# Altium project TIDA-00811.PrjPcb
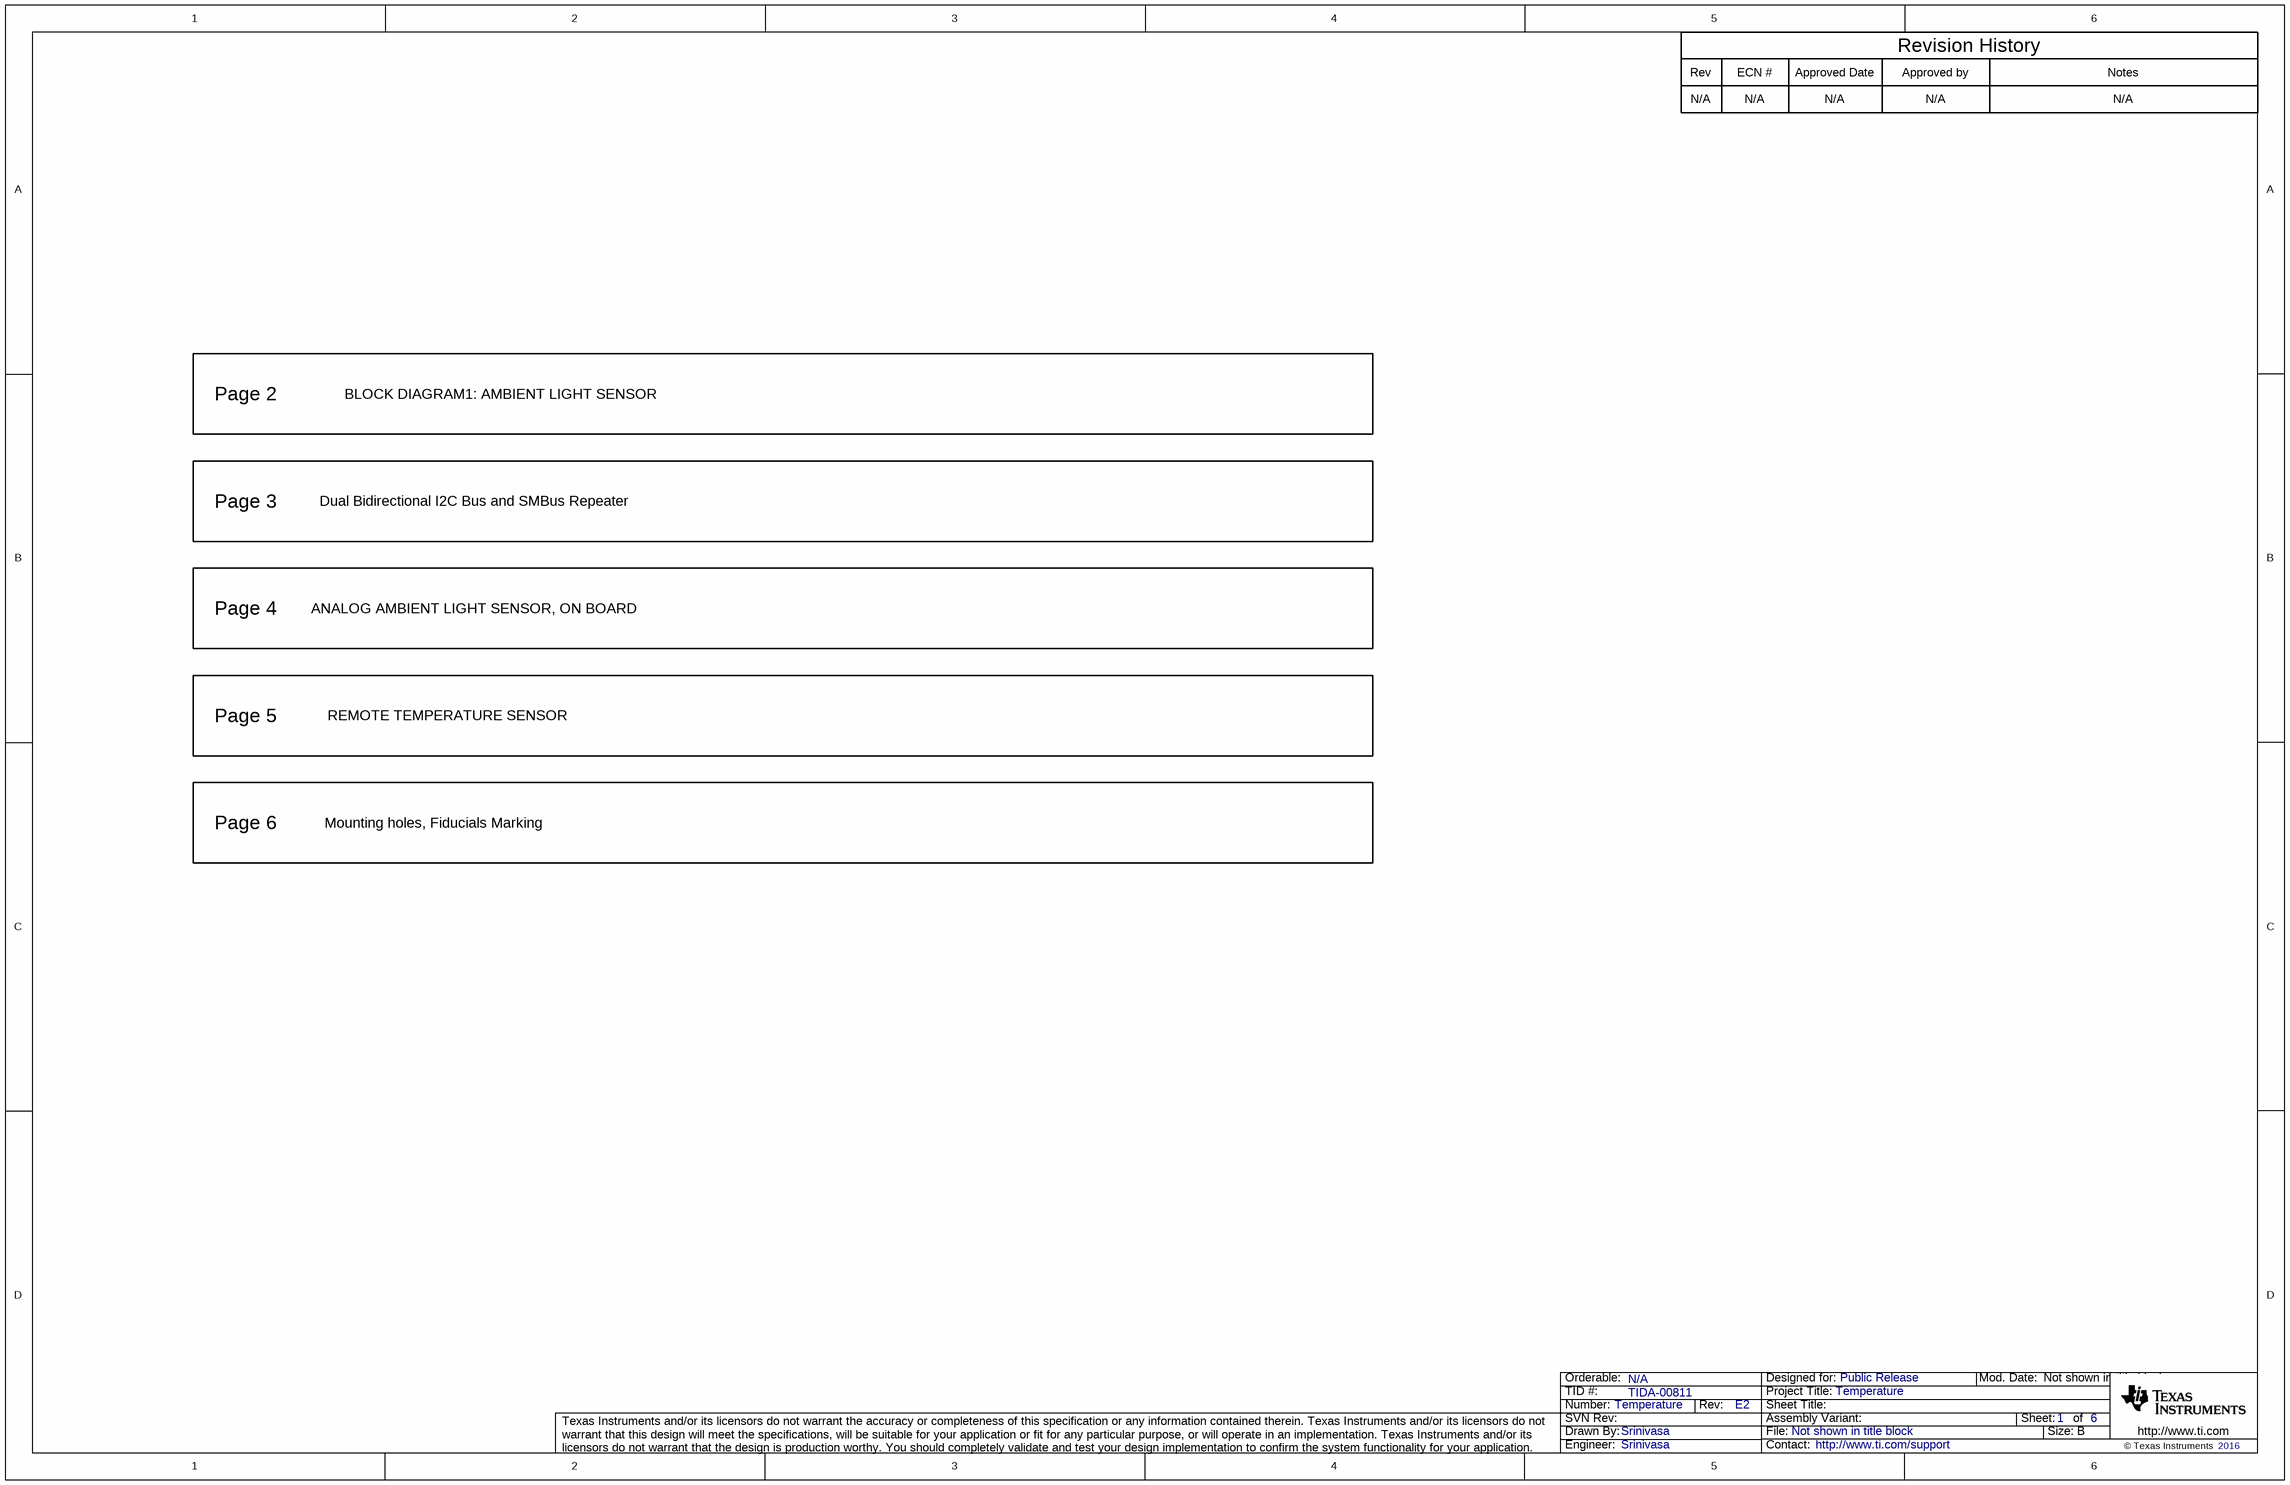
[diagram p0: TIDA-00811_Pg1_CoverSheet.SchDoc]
CopyrightYear: 2016; EVM_orderable: N/A; PCB_Layout: Manjunath M; PCB_Rev: E2; PRJ_Customer: Public Release; PRJ_Engineer: Srinivasa; PRJ_Number: Temperature; PRJ_Title: Temperature; SCH_Rev: E2; TechSupport: http://www.ti.com/support; TID: TIDA-00811
6 sheets, 185 parts. Net scope: flat (ports and power ports of the same name join across sheets).
Board file: TIDA-00811_PCB.PcbDoc
Sheets:
  TIDA-00811_Pg1_CoverSheet.SchDoc
  TIDA-00811_Pg2_Block Diagram.SchDoc
  TIDA-00811_Pg3.SchDoc
  TIDA-00811_Pg4.SchDoc
  TIDA-00811_Pg5.SchDoc
  TIDA-00811_Pg6_EVM_Hardware.SchDoc

## Sheet TIDA-00811_Pg1_CoverSheet.SchDoc
size 431 x 279 mm; Date: Not shown in title block; ApprovedBy: Not shown in title block; CheckedBy: Not shown in title block; Author: Not shown in title block; CompanyName: Not shown in title block; DrawnBy: Srinivasa; Engineer: Not shown in title block; Organization: Not shown in title block; Address1: Not shown in title block; Address2: Not shown in title block; Address3: Not shown in title block; Address4: Not shown in title block; DocumentNumber: 1; Revision: Use project parameter SCH_Rev; SheetNumber: 1; SheetTotal: 6; PageSetup: Record=PageOptions¦CenterHorizontal=True¦CenterVertical=True¦PrintScale=1.00¦XCorrection=1.00¦YCorrection=1.00¦PrintKind=0¦BorderSize=5000000¦LeftOffset=0¦BottomOffset=0¦Orientation=2¦PaperLength=1000¦PaperWidth=1000¦Scale=100¦PaperSource=15¦PrintQuality=600¦MediaType=1¦DitherType=10¦PaperKind=Letter¦PrintScaleMode=1

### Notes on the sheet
- Rev
- N/A
- ECN #
- Approved Date
- Approved by
- Revision History
- Notes
- Page 2
- BLOCK DIAGRAM1: AMBIENT LIGHT SENSOR
- Page 3
- Dual Bidirectional I2C Bus and SMBus Repeater
- Page 4
- ANALOG AMBIENT LIGHT SENSOR, ON BOARD
- Page 5
- REMOTE TEMPERATURE SENSOR
- Page 6
- Mounting holes, Fiducials Marking

## Sheet TIDA-00811_Pg2_Block Diagram.SchDoc
size 431 x 279 mm; Date: Not shown in title block; ApprovedBy: Not shown in title block; CheckedBy: Not shown in title block; Author: Not shown in title block; CompanyName: Not shown in title block; DrawnBy: Srinivasa; Engineer: Not shown in title block; Organization: Not shown in title block; Address1: Not shown in title block; Address2: Not shown in title block; Address3: Not shown in title block; Address4: Not shown in title block; DocumentNumber: 1; Revision: Use project parameter SCH_Rev; SheetNumber: 2; SheetTotal: 6; PageSetup: Record=PageOptions¦CenterHorizontal=True¦CenterVertical=True¦PrintScale=1.00¦XCorrection=1.00¦YCorrection=1.00¦PrintKind=0¦BorderSize=5000000¦LeftOffset=0¦BottomOffset=0¦Orientation=2¦PaperLength=1000¦PaperWidth=1000¦Scale=100¦PaperSource=15¦PrintQuality=600¦MediaType=1¦DitherType=10¦PaperKind=Letter¦PrintScaleMode=1
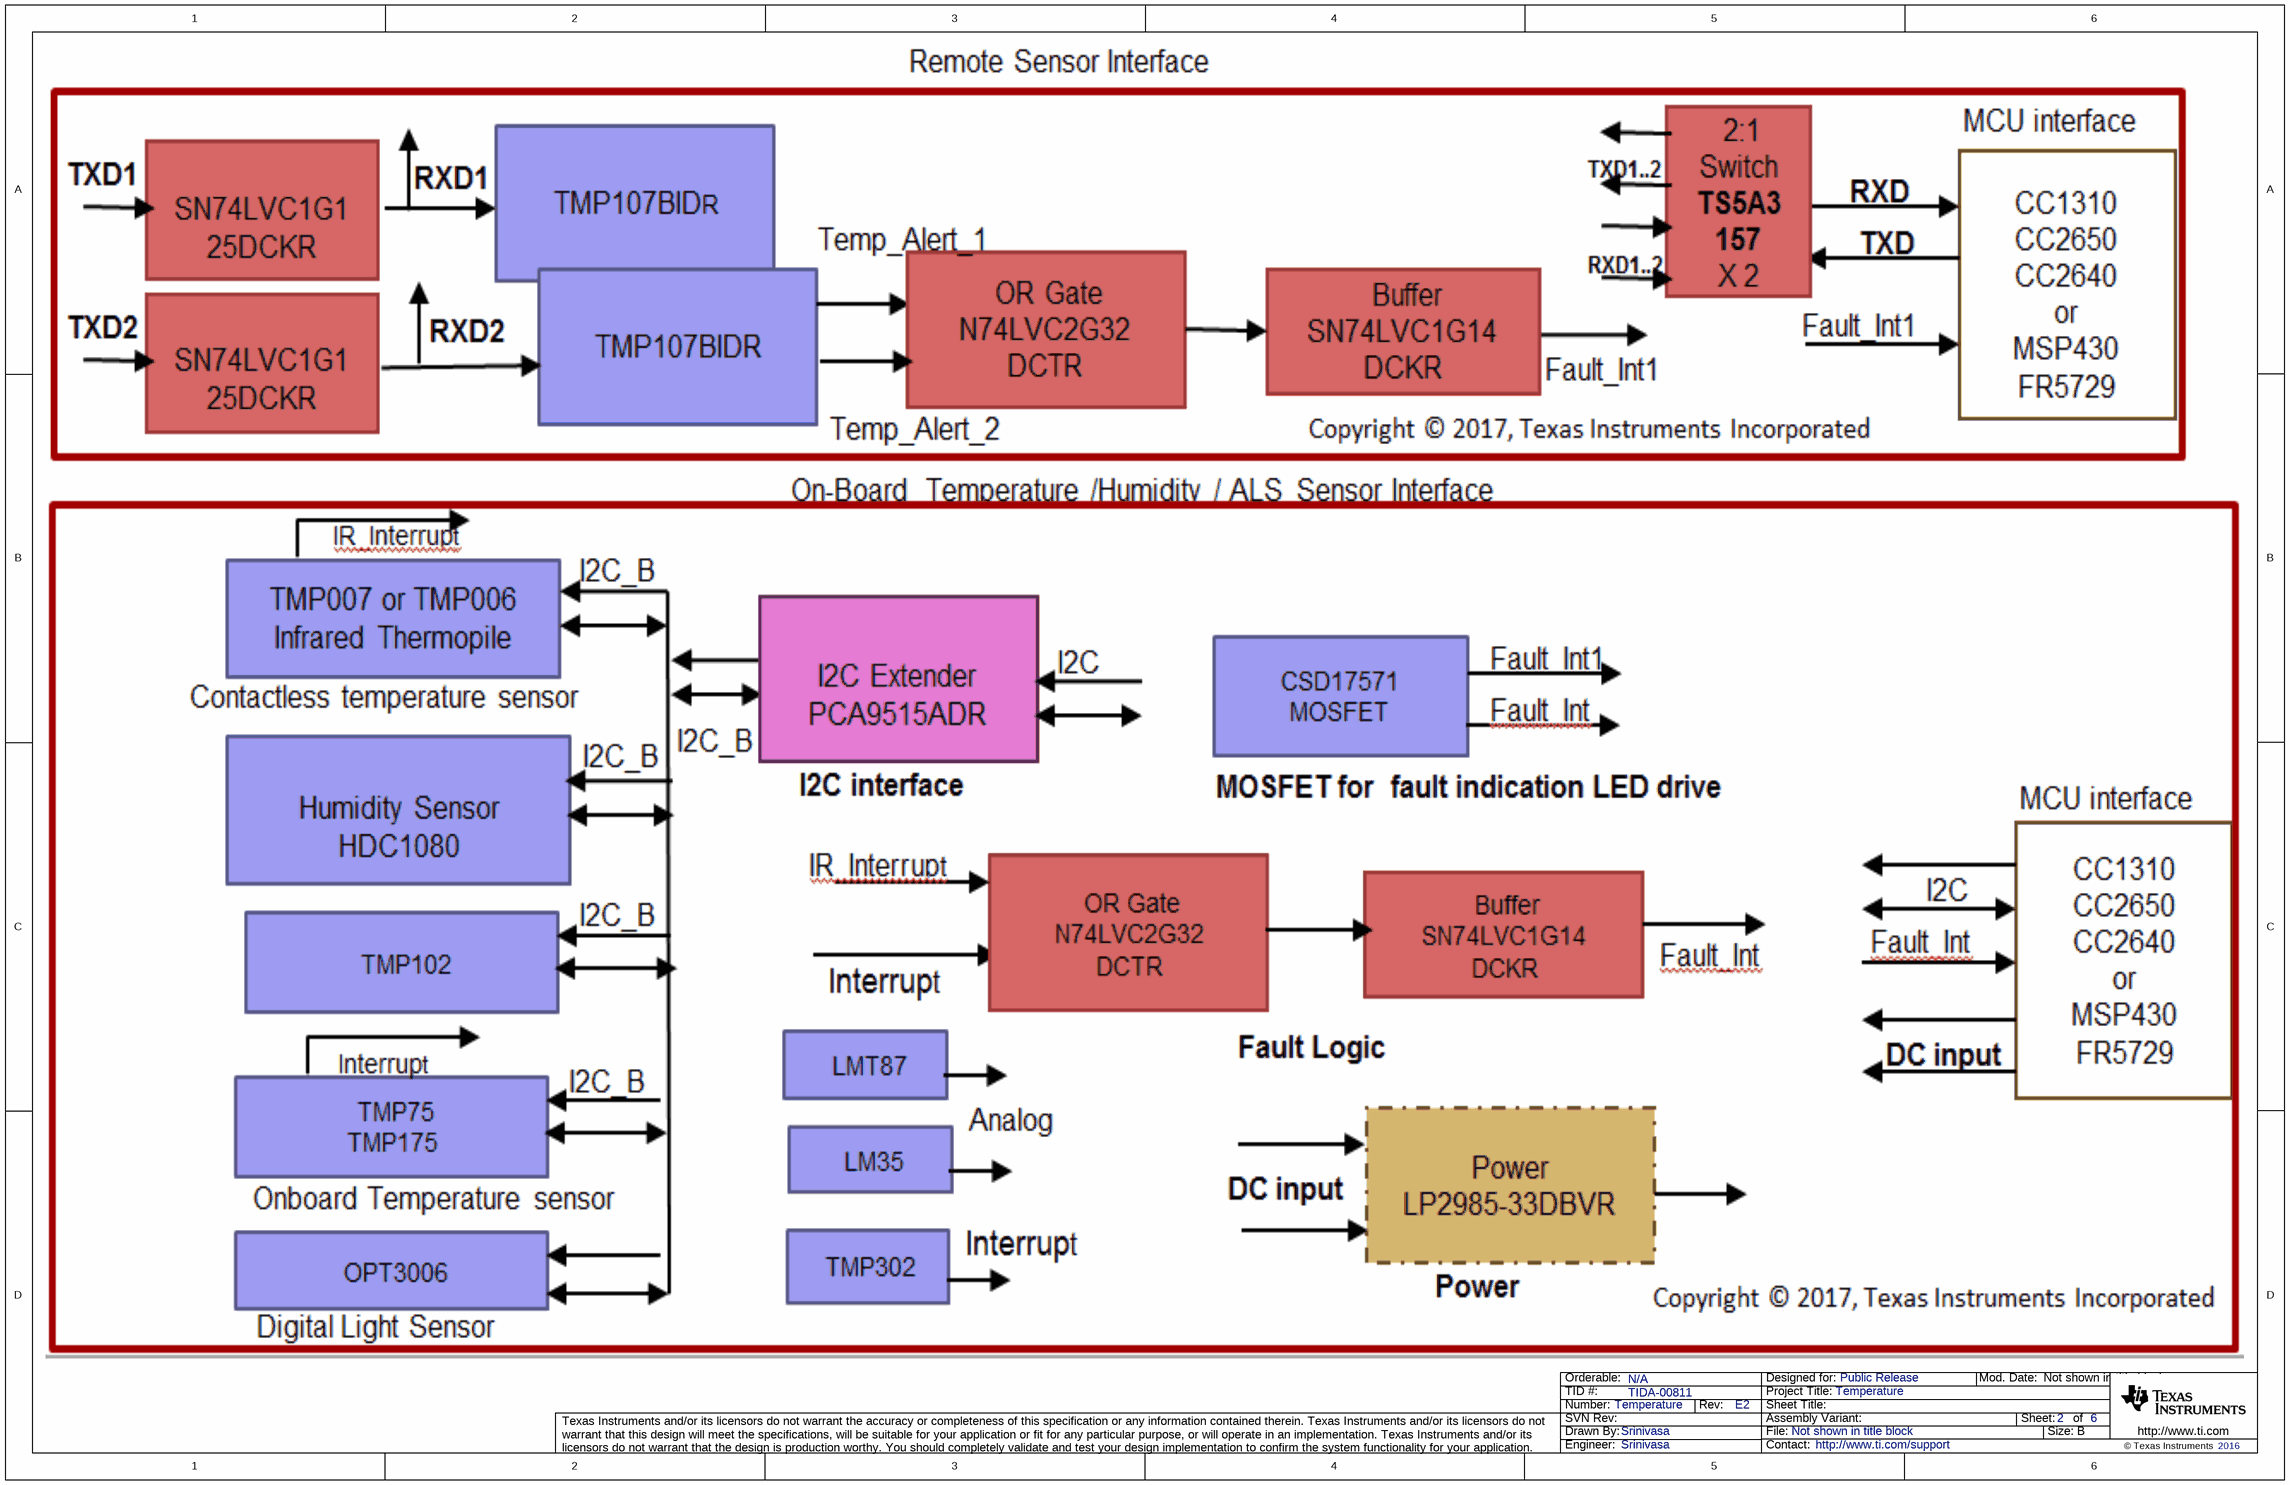
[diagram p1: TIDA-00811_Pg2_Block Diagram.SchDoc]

## Sheet TIDA-00811_Pg3.SchDoc
size 431 x 279 mm; Date: Not shown in title block; ApprovedBy: Not shown in title block; CheckedBy: Not shown in title block; Author: Not shown in title block; CompanyName: Not shown in title block; DrawnBy: Srinivasa; Engineer: Not shown in title block; Organization: Not shown in title block; Address1: Not shown in title block; Address2: Not shown in title block; Address3: Not shown in title block; Address4: Not shown in title block; DocumentNumber: 1; Revision: Use project parameter SCH_Rev; SheetNumber: 3; SheetTotal: 6; PageSetup: Record=PageOptions¦CenterHorizontal=True¦CenterVertical=True¦PrintScale=1.00¦XCorrection=1.00¦YCorrection=1.00¦PrintKind=0¦BorderSize=5000000¦LeftOffset=0¦BottomOffset=0¦Orientation=2¦PaperLength=1000¦PaperWidth=1000¦Scale=100¦PaperSource=15¦PrintQuality=600¦MediaType=1¦DitherType=10¦PaperKind=Letter¦PrintScaleMode=1
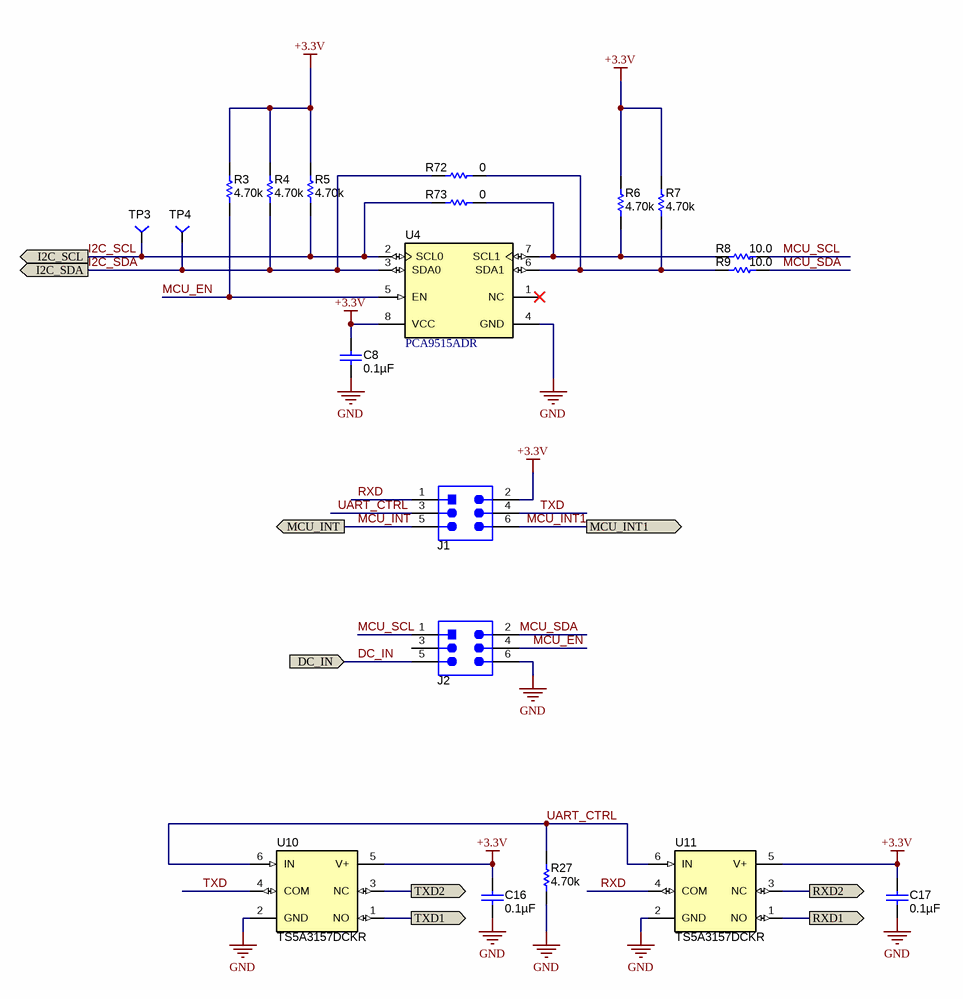
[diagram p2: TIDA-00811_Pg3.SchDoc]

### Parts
C8  ValueDisplayed: 0.1µF  [0603]  (hidden comment: 06033C104JAT2A)
C16  ValueDisplayed: 0.1µF  [0603]  (hidden comment: 06033C104JAT2A)
C17  ValueDisplayed: 0.1µF  [0603]  (hidden comment: 06033C104JAT2A)
J1  61300621121  [Mill-Max_802-10-006-10-001000]  (value not drawn)
J2  61300621121  [Mill-Max_802-10-006-10-001000]  (value not drawn)
R3  ValueDisplayed: 4.70k  [0603]  (hidden comment: RC0603FR-074K7L)
R4  ValueDisplayed: 4.70k  [0603]  (hidden comment: RC0603FR-074K7L)
R5  ValueDisplayed: 4.70k  [0603]  (hidden comment: RC0603FR-074K7L)
R6  ValueDisplayed: 4.70k  [0603]  (hidden comment: RC0603FR-074K7L)
R7  ValueDisplayed: 4.70k  [0603]  (hidden comment: RC0603FR-074K7L)
R8  ValueDisplayed: 10.0  [0603]  (hidden comment: CRCW060310R0FKEA)
R9  ValueDisplayed: 10.0  [0603]  (hidden comment: CRCW060310R0FKEA)
R27  ValueDisplayed: 4.70k  [0603]  (hidden comment: RC0603FR-074K7L)
R72  ValueDisplayed: 0  [0603]  (hidden comment: RC0603JR-070RL)
R73  ValueDisplayed: 0  [0603]  (hidden comment: RC0603JR-070RL)
TP3  TP-5001-BLACK  [TH-40]  (value not drawn)
TP4  TP-5001-BLACK  [TH-40]  (value not drawn)
U4  PCA9515ADR  [D0008A_N]
U10  TS5A3157DCKR  [DCK0006A_N]
U11  TS5A3157DCKR  [DCK0006A_N]

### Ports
DC_IN, I2C_SCL (out), I2C_SDA (out), MCU_INT1 (out), MCU_INT (out), RXD1 (out), RXD2 (out), TXD1 (out), TXD2 (out)

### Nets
+3.3V: C8.1 C16.1 C17.1 J1.2 R3.2 R4.2 R5.2 R6.2 R7.2 U4.8(VCC) U10.5(V+) U11.5(V+)
GND: C8.2 C16.2 C17.2 J2.6 R27.1 U4.4(GND) U10.2(GND) U11.2(GND)
DC_IN: J2.5 ; port DC_IN
I2C_SCL: R5.1 R73.2 TP3.1 U4.2(SCL0) ; port I2C_SCL
I2C_SDA: R4.1 R72.2 TP4.1 U4.3(SDA0) ; port I2C_SDA
MCU_EN: J2.4 R3.1 U4.5(EN)
MCU_INT: J1.5 ; port MCU_INT
MCU_INT1: J1.6 ; port MCU_INT1
MCU_SCL: J2.1 R8.2
MCU_SDA: J2.2 R9.2
RXD: J1.1 U11.4(COM)
RXD1: U11.1(NO) ; port RXD1
RXD2: U11.3(NC) ; port RXD2
TXD: J1.4 U10.4(COM)
TXD1: U10.1(NO) ; port TXD1
TXD2: U10.3(NC) ; port TXD2
UART_CTRL: J1.3 R27.2 U10.6(IN) U11.6(IN)
NetR6_1: R6.1 R8.1 R73.1 U4.7(SCL1)
NetR7_1: R7.1 R9.1 R72.1 U4.6(SDA1)

Not connected (* = marked no-connect by the designer): J2 3; U4 1(NC)*

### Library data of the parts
C8 C16 C17 = 06033C104JAT2A: CAP, CERM, 0.1 µF, 25 V, +/- 5%, X7R, 0603; Manufacturer: AVX; Polarized: N; CompType: Capacitor; Value: 0.1uF; U/M: EA; Cap_F: 0.0000001; Tolerance_%: 5; ESR_ohm: 0.05; Value1: 0.05 ohm; VDC_V: 25; Value2: 25V; TaMin_C: -55; TaMax_C: 125; AEC Category: Q200
J1 J2 = 802-10-006-10-001000: Header, 2.54 mm, 3x2, Gold, TH; Manufacturer: Mill-Max; SymbolCreator: a0412235; Pitch_mm: 2.54; Gender: Male; Shrouded: N; Row_Count: 2
R3-R7 R27 = RC0603FR-074K7L: RES, 4.70 k, 1%, 0.1 W, 0603; Manufacturer: Yageo America; CompType: Resistor; Value: 4.70k; Res_ohm: 4700; Value_Code: 4k70; Tolerance_%: 1; Power_W: 0.1; Value2: 0.1W; VDC_V: 150; TempCo: 200 ppm/C; U/M: EA; AEC Category: Q200
R8 R9 = CRCW060310R0FKEA: RES, 10.0, 1%, 0.1 W, 0603; Manufacturer: Vishay-Dale; CompType: Resistor; Value: 10.0; Res_ohm: 10; Value_Code: 10R0; Tolerance_%: 1; Power_W: 0.1; Value2: 0.1W; VDC_V: 75; TempCo: 100 ppm/C; SizeArea_mm2: 1.28; SizeX_mm: 1.6; SizeY_mm: 0.8; EIA_Code: E96; U/M: EA; AEC Category: Q200
R72 R73 = RC0603JR-070RL: RES, 0, 5%, 0.1 W, 0603; Manufacturer: Yageo America; CompType: Resistor; Value: 0; Value_Code: 0000; Tolerance_%: 5; Power_W: 0.1; Value2: 0.1W; VDC_V: 50; TempCo: 200 ppm/C; SizeArea_mm2: 1.28; SizeX_mm: 1.6; SizeY_mm: 0.8; SizeZ_mm: 1; EIA_Code: E24; U/M: EA; AEC Category: Q200
TP3 TP4 = TP-5001-BLACK: Test Point,  Black, Thru Hole Color Keyed; Manufacturer: Keystone; PartNumber: 5001; area: 10.000; Value: 5001
U4 = PCA9515ADR: Dual Bidirectional I2C Bus and SMBus Repeater, 2 Channel Width, 2.3 to 3.6 V, -40 to 85 degC, 8-pin SOIC (D), Green (RoHS & no Sb/Br); Manufacturer: Texas Instruments; Alternate PartNumber: Equivalent; SubFamily: I2C Hub, Buffer, Repeater; No. of Outputs: 2; VCC(Max)(V): 3.6; VCC(Min)(V): 2.3; Max Frequency(kHz): 400; Vcc range(V): 2.3 to 5.5; 5V Tolerant I/O: Yes
U10 U11 = TS5A3157DCKR: 10-OHM SPDT ANALOG SWITCH, DCK0006A (SOT-SC70-6); Manufacturer: Texas Instruments; SymbolCreator: a0411947; SizeArea_mm2: 4.2; SizeAreaWB_mm2: 9.3; SizeX_mm: 2.1; SizeY_mm: 2; SizeZ_mm: 1.1; CompType: IC; U/M: EA

## Sheet TIDA-00811_Pg4.SchDoc
size 431 x 279 mm; Date: Not shown in title block; ApprovedBy: Not shown in title block; CheckedBy: Not shown in title block; Author: Not shown in title block; CompanyName: Not shown in title block; DrawnBy: Srinivasa; Engineer: Not shown in title block; Organization: Not shown in title block; Address1: Not shown in title block; Address2: Not shown in title block; Address3: Not shown in title block; Address4: Not shown in title block; DocumentNumber: 1; Revision: Use project parameter SCH_Rev; SheetNumber: 4; SheetTotal: 6; PageSetup: Record=PageOptions¦CenterHorizontal=True¦CenterVertical=True¦PrintScale=1.00¦XCorrection=1.00¦YCorrection=1.00¦PrintKind=0¦BorderSize=5000000¦LeftOffset=0¦BottomOffset=0¦Orientation=2¦PaperLength=1000¦PaperWidth=1000¦Scale=100¦PaperSource=15¦PrintQuality=600¦MediaType=1¦DitherType=10¦PaperKind=Letter¦PrintScaleMode=1
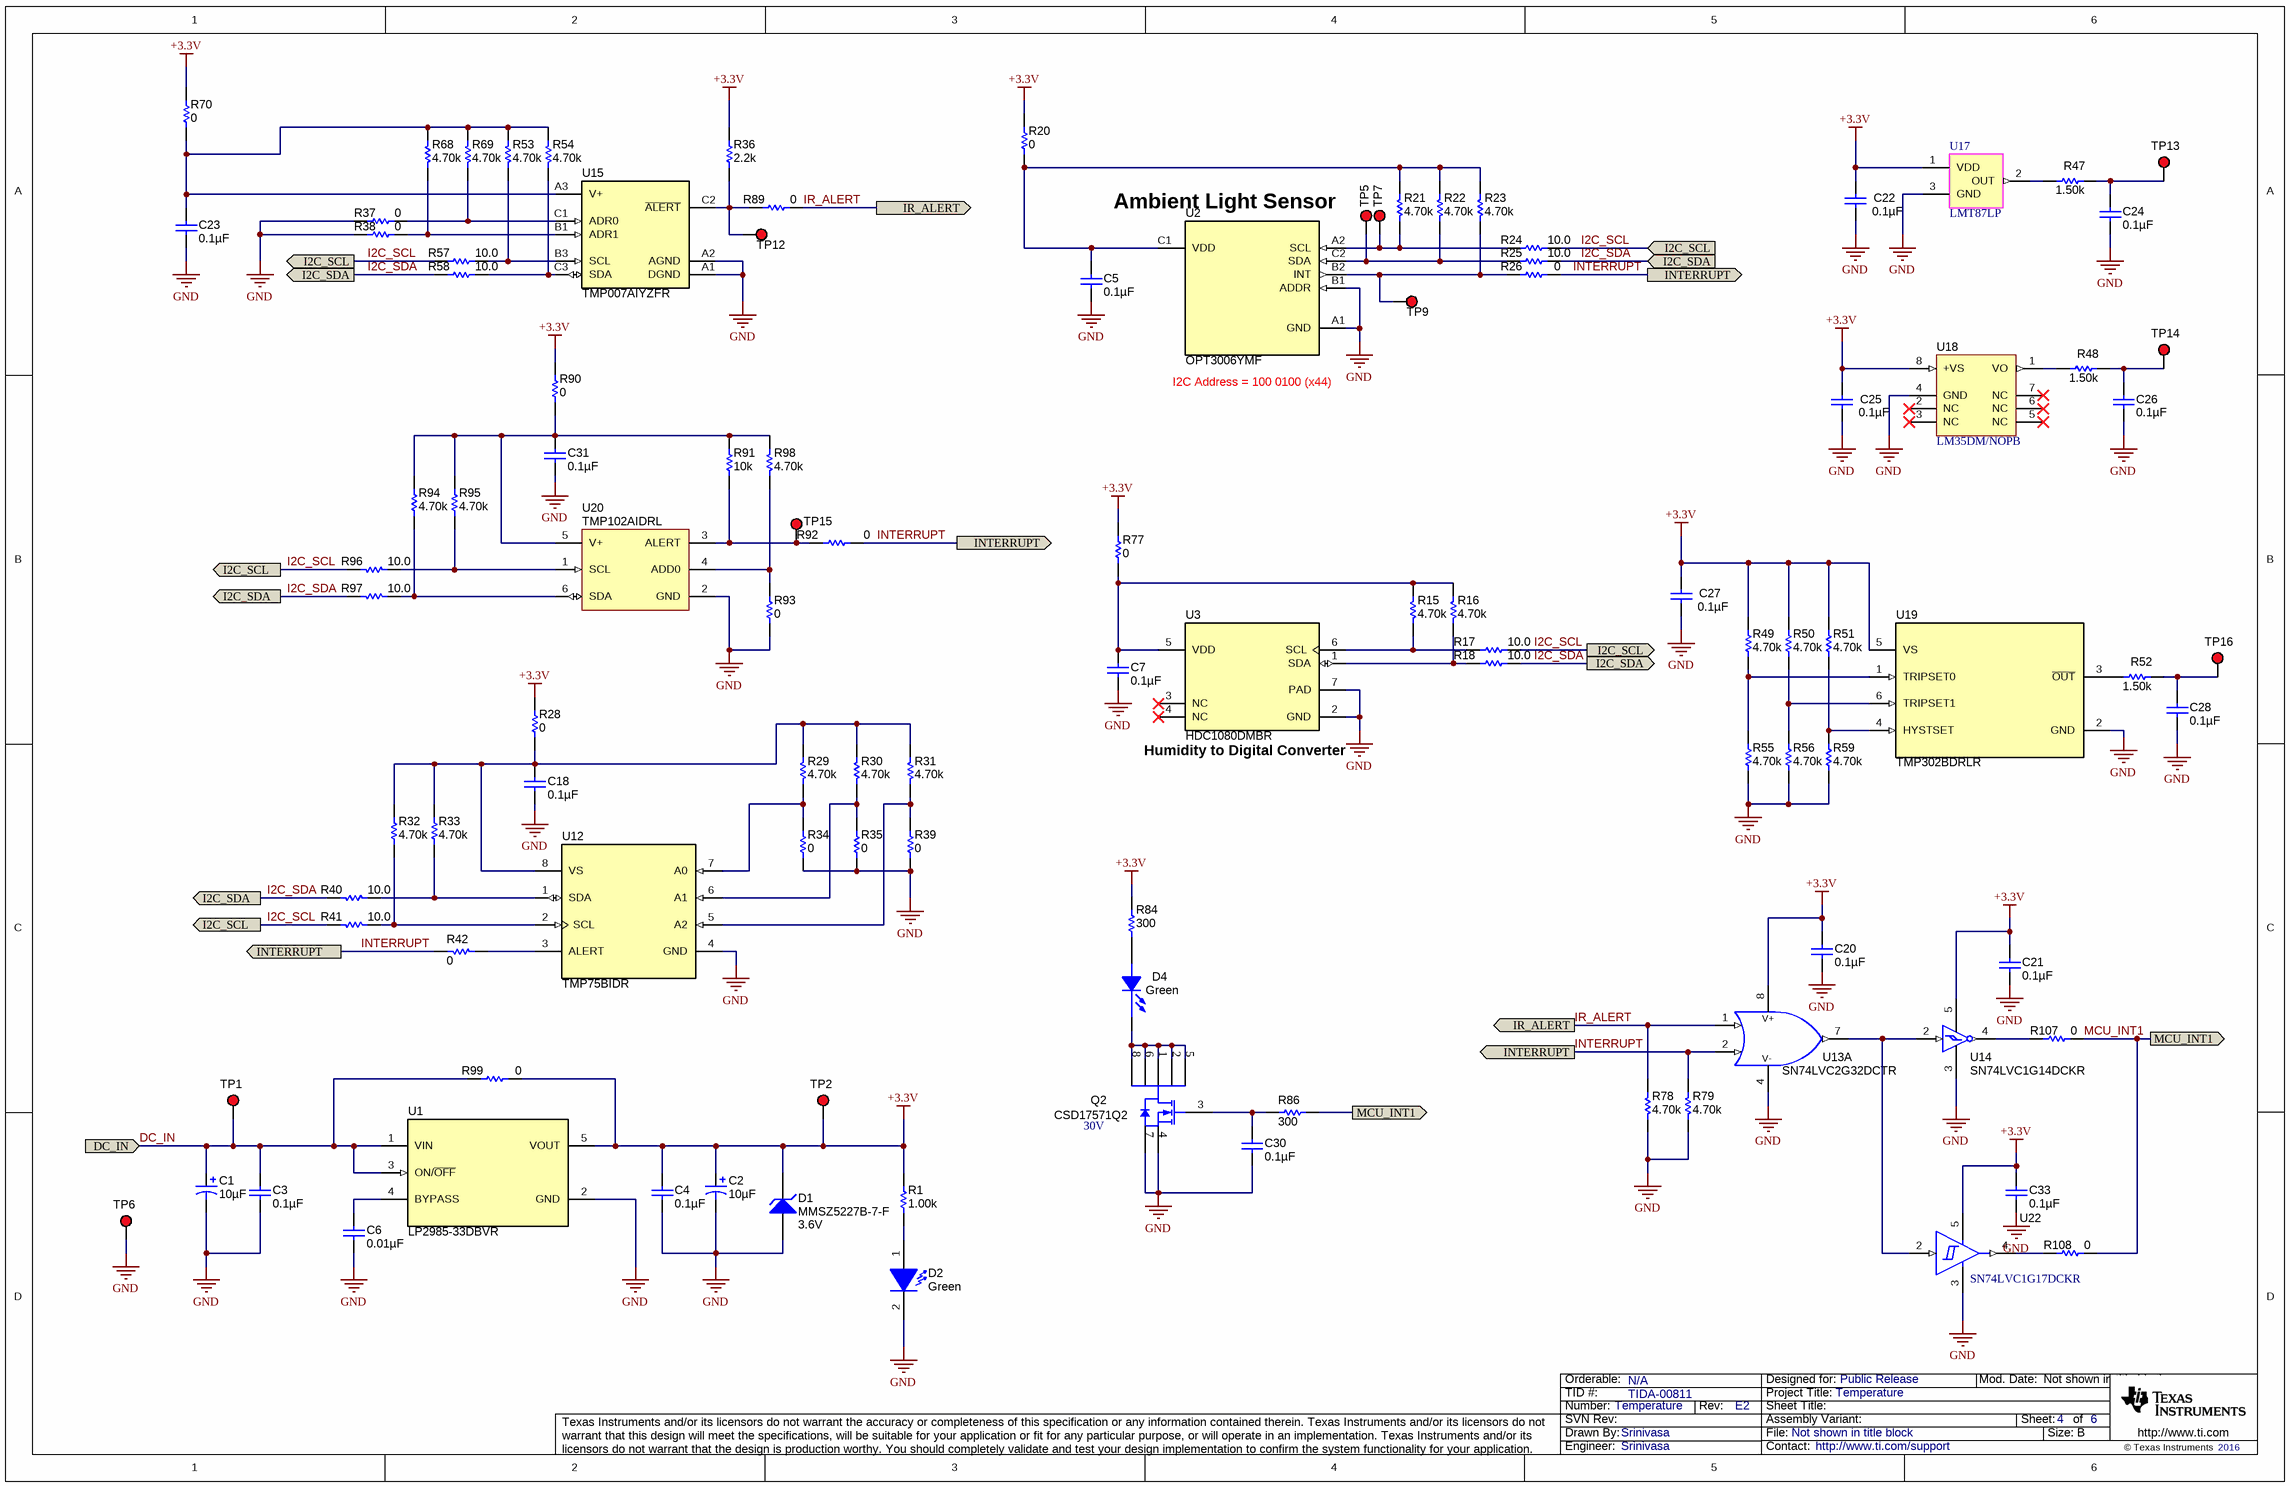
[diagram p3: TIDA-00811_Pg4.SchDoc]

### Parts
C1  ValueDisplayed: 10µF  [6032-28]  (hidden comment: 293D106X9025C2TE3)
C2  ValueDisplayed: 10µF  [6032-28]  (hidden comment: 293D106X9025C2TE3)
C3  ValueDisplayed: 0.1µF  [0603]  (hidden comment: 06033C104JAT2A)
C4  ValueDisplayed: 0.1µF  [0603]  (hidden comment: 06033C104JAT2A)
C5  ValueDisplayed: 0.1µF  [0603]  (hidden comment: 06033C104JAT2A)
C6  ValueDisplayed: 0.01µF  [0603]  (hidden comment: C1608C0G1E103J080AA)
C7  ValueDisplayed: 0.1µF  [0603]  (hidden comment: 06033C104JAT2A)
C18  ValueDisplayed: 0.1µF  [0603]  (hidden comment: 06033C104JAT2A)
C20  ValueDisplayed: 0.1µF  [0603]  (hidden comment: 06033C104JAT2A)
C21  ValueDisplayed: 0.1µF  [0603]  (hidden comment: 06033C104JAT2A)
C22  ValueDisplayed: 0.1µF  [0603]  (hidden comment: 06033C104JAT2A)
C23  ValueDisplayed: 0.1µF  [0603]  (hidden comment: 06033C104JAT2A)
C24  ValueDisplayed: 0.1µF  [0603]  (hidden comment: 06033C104JAT2A)
C25  ValueDisplayed: 0.1µF  [0603]  (hidden comment: 06033C104JAT2A)
C26  ValueDisplayed: 0.1µF  [0603]  (hidden comment: 06033C104JAT2A)
C27  ValueDisplayed: 0.1µF  [0603]  (hidden comment: 06033C104JAT2A)
C28  ValueDisplayed: 0.1µF  [0603]  (hidden comment: 06033C104JAT2A)
C30  ValueDisplayed: 0.1µF  [0603]  (hidden comment: 06033C104JAT2A)
C31  ValueDisplayed: 0.1µF  [0603]  (hidden comment: 06033C104JAT2A)
C33  ValueDisplayed: 0.1µF  [0603]  (hidden comment: 06033C104JAT2A)
D1  MMSZ5227B-7-F  value 3.6V  [SOD-123]
D2  value Green  [LG L29K_GREEN]  (hidden comment: LG L29K-G2J1-24-Z)
D4  value Green  [LED0603AA]  (hidden comment: LED_LG L29K-G2J1-24-Z)
Q2  CSD17571Q2  value 30V  [SON_CSD17571Q2]
R1  ValueDisplayed: 1.00k  [0603]  (hidden comment: RC0603FR-071KL)
R15  ValueDisplayed: 4.70k  [0603]  (hidden comment: RC0603FR-074K7L)
R16  ValueDisplayed: 4.70k  [0603]  (hidden comment: RC0603FR-074K7L)
R17  ValueDisplayed: 10.0  [0603]  (hidden comment: CRCW060310R0FKEA)
R18  ValueDisplayed: 10.0  [0603]  (hidden comment: CRCW060310R0FKEA)
R20  ValueDisplayed: 0  [0603]  (hidden comment: RC0603JR-070RL)
R21  ValueDisplayed: 4.70k  [0603]  (hidden comment: RC0603FR-074K7L)
R22  ValueDisplayed: 4.70k  [0603]  (hidden comment: RC0603FR-074K7L)
R23  ValueDisplayed: 4.70k  [0603]  (hidden comment: RC0603FR-074K7L)
R24  ValueDisplayed: 10.0  [0603]  (hidden comment: CRCW060310R0FKEA)
R25  ValueDisplayed: 10.0  [0603]  (hidden comment: CRCW060310R0FKEA)
R26  ValueDisplayed: 0  [0603]  (hidden comment: RC0603JR-070RL)
R28  ValueDisplayed: 0  [0603]  (hidden comment: RC0603JR-070RL)
R29  ValueDisplayed: 4.70k  [0603]  (hidden comment: RC0603FR-074K7L)
R30  ValueDisplayed: 4.70k  [0603]  (hidden comment: RC0603FR-074K7L)
R31  ValueDisplayed: 4.70k  [0603]  (hidden comment: RC0603FR-074K7L)
R32  ValueDisplayed: 4.70k  [0603]  (hidden comment: RC0603FR-074K7L)
R33  ValueDisplayed: 4.70k  [0603]  (hidden comment: RC0603FR-074K7L)
R34  ValueDisplayed: 0  [0603]  (hidden comment: RC0603JR-070RL)
R35  ValueDisplayed: 0  [0603]  (hidden comment: RC0603JR-070RL)
R36  ValueDisplayed: 2.2k  [0603]  (hidden comment: RC0603JR-072K2L)
R37  ValueDisplayed: 0  [0603]  (hidden comment: RC0603JR-070RL)
R38  ValueDisplayed: 0  [0603]  (hidden comment: RC0603JR-070RL)
R39  ValueDisplayed: 0  [0603]  (hidden comment: RC0603JR-070RL)
R40  ValueDisplayed: 10.0  [0603]  (hidden comment: CRCW060310R0FKEA)
R41  ValueDisplayed: 10.0  [0603]  (hidden comment: CRCW060310R0FKEA)
R42  ValueDisplayed: 0  [0603]  (hidden comment: RC0603JR-070RL)
R47  ValueDisplayed: 1.50k  [0603]  (hidden comment: CRCW06031K50FKEA)
R48  ValueDisplayed: 1.50k  [0603]  (hidden comment: CRCW06031K50FKEA)
R49  ValueDisplayed: 4.70k  [0603]  (hidden comment: RC0603FR-074K7L)
R50  ValueDisplayed: 4.70k  [0603]  (hidden comment: RC0603FR-074K7L)
R51  ValueDisplayed: 4.70k  [0603]  (hidden comment: RC0603FR-074K7L)
R52  ValueDisplayed: 1.50k  [0603]  (hidden comment: CRCW06031K50FKEA)
R53  ValueDisplayed: 4.70k  [0603]  (hidden comment: RC0603FR-074K7L)
R54  ValueDisplayed: 4.70k  [0603]  (hidden comment: RC0603FR-074K7L)
R55  ValueDisplayed: 4.70k  [0603]  (hidden comment: RC0603FR-074K7L)
R56  ValueDisplayed: 4.70k  [0603]  (hidden comment: RC0603FR-074K7L)
R57  ValueDisplayed: 10.0  [0603]  (hidden comment: CRCW060310R0FKEA)
R58  ValueDisplayed: 10.0  [0603]  (hidden comment: CRCW060310R0FKEA)
R59  ValueDisplayed: 4.70k  [0603]  (hidden comment: RC0603FR-074K7L)
R68  ValueDisplayed: 4.70k  [0603]  (hidden comment: RC0603FR-074K7L)
R69  ValueDisplayed: 4.70k  [0603]  (hidden comment: RC0603FR-074K7L)
R70  ValueDisplayed: 0  [0603]  (hidden comment: RC0603JR-070RL)
R77  ValueDisplayed: 0  [0603]  (hidden comment: RC0603JR-070RL)
R78  ValueDisplayed: 4.70k  [0603]  (hidden comment: RC0603FR-074K7L)
R79  ValueDisplayed: 4.70k  [0603]  (hidden comment: RC0603FR-074K7L)
R84  value 300  [0603]  (hidden comment: CRCW0603300RJNEA)
R86  value 300  [0603]  (hidden comment: CRCW0603300RJNEA)
R89  ValueDisplayed: 0  [0603]  (hidden comment: RC0603JR-070RL)
R90  ValueDisplayed: 0  [0603]  (hidden comment: RC0603JR-070RL)
R91  ValueDisplayed: 10k  [0603]  (hidden comment: CRCW060310K0JNEA)
R92  ValueDisplayed: 0  [0603]  (hidden comment: RC0603JR-070RL)
R93  ValueDisplayed: 0  [0603]  (hidden comment: RC0603JR-070RL)
R94  ValueDisplayed: 4.70k  [0603]  (hidden comment: RC0603FR-074K7L)
R95  ValueDisplayed: 4.70k  [0603]  (hidden comment: RC0603FR-074K7L)
R96  ValueDisplayed: 10.0  [0603]  (hidden comment: CRCW060310R0FKEA)
R97  ValueDisplayed: 10.0  [0603]  (hidden comment: CRCW060310R0FKEA)
R98  ValueDisplayed: 4.70k  [0603]  (hidden comment: RC0603FR-074K7L)
R99  ValueDisplayed: 0  [0805_HV]  (hidden comment: CRCW08050000Z0EA)
R107  ValueDisplayed: 0  [0603]  (hidden comment: RC0603JR-070RL)
R108  ValueDisplayed: 0  [0603]  (hidden comment: RC0603JR-070RL)
TP1  5000  [Keystone5000]  (value not drawn)
TP2  5000  [Keystone5000]  (value not drawn)
TP5  5000  [Keystone5000]  (value not drawn)
TP6  5000  [Keystone5000]  (value not drawn)
TP7  5000  [Keystone5000]  (value not drawn)
TP9  5000  [Keystone5000]  (value not drawn)
TP12  5000  [Keystone5000]  (value not drawn)
TP13  5000  [Keystone5000]  (value not drawn)
TP14  5000  [Keystone5000]  (value not drawn)
TP15  5000  [Keystone5000]  (value not drawn)
TP16  5000  [Keystone5000]  (value not drawn)
U1  LP2985-33DBVR  [DBV0005A_N]
U2  OPT3006YMF  [YMF0006A]
U3  HDC1080DMBR  [DMB0006A]
U12  TMP75BIDR  [D0008A_N]
U13  SN74LVC2G32DCTR  [DCT0008A_N]  (part A of 2)
U14  SN74LVC1G14DCKR  [DCK0005A_N]
U15  TMP007AIYZFR  [YZF0008AEAE]
U17  LMT87LP  [LP0003A]
U18  LM35DM/NOPB  [M08A_N]
U19  TMP302BDRLR  [DRL0006A]
U20  TMP102AIDRL  [DRL0006A_N]
U22  SN74LVC1G17DCKR  [DCK0005A_N]

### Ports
DC_IN, I2C_SCL (in), I2C_SCL (out), I2C_SDA (in), I2C_SDA (out), INTERRUPT (out), IR_ALERT (out), MCU_INT1 (out)

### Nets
+3.3V: C2.1(+) C4.1 C20.2 C21.2 C22.1 C25.1 C27.1 C33.2 D1.1(K) R1.2 R20.2 R28.2 R36.2 R49.2 R50.2 R51.2 R70.2 R77.2 R84.2 R90.2 R99.2 TP2.1 U1.5(VOUT) U13.8(VCC) U14.5(VCC) U17.1(VDD) U18.8(+VS) U19.5(VS) U22.5(VCC)
GND: C1.2(-) C2.2(-) C3.2 C4.2 C5.1 C6.2 C7.1 C18.1 C20.1 C21.1 C22.2 C23.1 C24.1 C25.2 C26.1 C27.2 C28.1 C30.2 C31.1 C33.1 D1.2(A) D2.2(K) Q2.4(S) Q2.7(S) R34.2 R35.2 R37.1 R38.1 R39.2 R55.1 R56.1 R59.1 R78.2 R79.2 R93.2 TP6.1 U1.2(GND) U2.A1(GND) U2.B1(ADDR) U3.2(GND) U3.7(PAD) U12.4(GND) U13.4(GND) U14.3(GND) U15.A1(DGND) U15.A2(AGND) U17.3(GND) U18.4(GND) U19.2(GND) U20.2(GND) U22.3(GND)
DC_IN: C1.1(+) C3.1 R99.1 TP1.1 U1.1(VIN) U1.3(ON/~{OFF}) ; port DC_IN
I2C_SCL: R17.2 R24.2 R41.2 R57.1 R96.2 ; port I2C_SCL
I2C_SDA: R18.2 R25.2 R40.2 R58.1 R97.2 ; port I2C_SDA
INTERRUPT: R26.2 R42.2 R79.1 R92.2 U13.2(1B) ; port INTERRUPT
IR_ALERT: R78.1 R89.2 U13.1(1A) ; port IR_ALERT
MCU_INT1: R86.1 R107.2 R108.2 ; port MCU_INT1
NetC5_2: C5.2 R20.1 R21.2 R22.2 R23.2 U2.C1(VDD)
NetC6_1: C6.1 U1.4(BYPASS)
NetC7_2: C7.2 R15.2 R16.2 R77.1 U3.5(VDD)
NetC18_2: C18.2 R28.1 R29.2 R30.2 R31.2 R32.2 R33.2 U12.8(VS)
NetC23_2: C23.2 R53.2 R54.2 R68.2 R69.2 R70.1 U15.A3(V+)
NetC24_2: C24.2 R47.2 TP13.1
NetC26_2: C26.2 R48.2 TP14.1
NetC28_2: C28.2 R52.2 TP16.1
NetC30_1: C30.1 Q2.3(G) R86.2
NetC31_2: C31.2 R90.1 R91.2 R94.2 R95.2 R98.2 U20.5(V+)
NetD2_1: D2.1(A) R1.1
NetD4_1: D4.1(C) Q2.1(D) Q2.2(D) Q2.5(D) Q2.6(D) Q2.8(D)
NetD4_2: D4.2(A) R84.1
NetR15_1: R15.1 R17.1 U3.6(SCL)
NetR16_1: R16.1 R18.1 U3.1(SDA)
NetR21_1: R21.1 R24.1 TP7.1 U2.A2(SCL)
NetR22_1: R22.1 R25.1 TP5.1 U2.C2(SDA)
NetR23_1: R23.1 R26.1 TP9.1 U2.B2(INT)
NetR29_1: R29.1 R34.1 U12.7(A0)
NetR30_1: R30.1 R35.1 U12.6(A1)
NetR31_1: R31.1 R39.1 U12.5(A2)
NetR32_1: R32.1 R41.1 U12.2(SCL)
NetR33_1: R33.1 R40.1 U12.1(SDA)
NetR36_1: R36.1 R89.1 TP12.1 U15.C2(~{ALERT})
NetR37_2: R37.2 R69.1 U15.C1(ADR0)
NetR38_2: R38.2 R68.1 U15.B1(ADR1)
NetR42_1: R42.1 U12.3(ALERT)
NetR47_1: R47.1 U17.2(OUT)
NetR48_1: R48.1 U18.1(VO)
NetR49_1: R49.1 R55.2 U19.1(TRIPSET0)
NetR50_1: R50.1 R56.2 U19.6(TRIPSET1)
NetR51_1: R51.1 R59.2 U19.4(HYSTSET)
NetR52_1: R52.1 U19.3(~{OUT})
NetR53_1: R53.1 R57.2 U15.B3(SCL)
NetR54_1: R54.1 R58.2 U15.C3(SDA)
NetR91_1: R91.1 R92.1 TP15.1 U20.3(ALERT)
NetR93_1: R93.1 R98.1 U20.4(ADD0)
NetR94_1: R94.1 R97.1 U20.6(SDA)
NetR95_1: R95.1 R96.1 U20.1(SCL)
NetR107_1: R107.1 U14.4(Y)
NetR108_1: R108.1 U22.4(Y)
NetU13_7: U13.7(1Y) U14.2(A) U22.2(A)

Not connected (* = marked no-connect by the designer): U3 3(NC)* 4(NC)*; U18 2(NC)* 3(NC)* 5(NC)* 6(NC)* 7(NC)*

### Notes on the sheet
- Ambient Light Sensor
- (near U2) I2C Address = 100 0100 (x44)
- (near U3) Humidity to Digital Converter

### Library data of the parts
C1 C2 = 293D106X9025C2TE3: CAP, TA, 10 µF, 25 V, +/- 10%, 1.5 ohm, SMD; Manufacturer: Vishay-Sprague; Polarized: Y; CompType: Capacitor; Value: 10uF; U/M: EA; Cap_F: 0.00001; Tolerance_%: 10; Value1: 1.5 ohm; VDC_V: 25; Value2: 25V; ESR_ohm: 1.5; IRMS_A: 0.27; TaMin_C: -55; TaMax_C: 125; Cap_Case: C; AEC Category: Q200
C3-C5 C7 C18 C20 C21 C23 C31 C33 = 06033C104JAT2A: as C8 on sheet TIDA-00811_Pg3
C6 = C1608C0G1E103J: CAP, CERM, 0.01 µF, 25 V, +/- 5%, C0G/NP0, 0603; Manufacturer: TDK; Polarized: N; CompType: Capacitor; Value: 0.01uF; U/M: EA; Cap_F: 0.00000001; Tolerance_%: 5; Value1: Unknown; VDC_V: 25; Value2: 25V; TaMin_C: -55; TaMax_C: 125; AEC Category: Q200
C22 C24-C28 C30 = 06033C104JAT2A: CAP, CERM, 0.1uF, 25V, +/-5%, X7R, 0603; Manufacturer: AVX; Polarized: N; CompType: Capacitor; U/M: EA; Cap_F: 0.0000001; Tolerance_%: 5; ESR_Ohm: 0.05; Value1: 0.05 ohm; VDC_V: 25; TaMin_C: -55; TaMax_C: 125
D1 = MMSZ5227B-7-F: Diode, Zener, 3.6 V, 500 mW, SOD-123; Manufacturer: Diodes Inc.; SymbolCreator: a0412235; U/M: EA; Power_W: 0.5; Vz_V: 3.6; Value1: 0.5W; RJA_CperW: 350; AEC Category: Q101
D2 = LG L29K-G2J1-24-Z: LED, Green, SMD; Manufacturer: OSRAM; Vf_V: 1.7; Value2: 1.7V; Io_A: 0.002; Tjmax_C: 110; Value1: W; U/M: EA
D4 = LED_LG L29K-G2J1-24-Z: LED SmartLED Green 570NM; Manufacturer: OSRAM; SymbolCreator: x0120606
Q2 = CSD17571Q2: MOSFET, N-CH, 30V, 22A, SON 2X2 MM; Manufacturer: TEXAS INSTRUMENTS; CompType: POWER MOSFET
R1 = RC0603FR-071KL: RES, 1.00 k, 1%, 0.1 W, 0603; Manufacturer: Yageo America; CompType: Resistor; Value: 1.00k; Res_ohm: 1000; Value_Code: 1k00; Tolerance_%: 1; Power_W: 0.1; Value2: 0.1W; VDC_V: 150; TempCo: 200 ppm/C; EIA_Code: E96; U/M: EA; AEC Category: Q200
R15 R16 R21-R23 R29-R33 R49-R51 R53-R56 R59 R68 R69 R78 R79 R94 R95 R98 = RC0603FR-074K7L: as R3 on sheet TIDA-00811_Pg3
R17 R18 R24 R25 R40 R41 R57 R58 R96 R97 = CRCW060310R0FKEA: as R8 on sheet TIDA-00811_Pg3
R20 R26 R28 R34 R35 R37-R39 R42 R70 R77 R89 R90 R92 R93 R107 R108 = RC0603JR-070RL: RES, 0, 5%, 0.1 W, 0603; Manufacturer: Yageo America; CompType: Resistor; Value: 0; Value_Code: 0000; Tolerance_%: 5; Power_W: 0.1; Value2: 0.1W; VDC_V: 50; TempCo: 200 ppm/C; EIA_Code: E24; U/M: EA; AEC Category: Q200
R36 = RC0603JR-072K2L: RES, 2.2 k, 5%, 0.1 W, 0603; Manufacturer: Yageo America; CompType: Resistor; Value: 2.2k; Res_ohm: 2200; Value_Code: 2k20; Tolerance_%: 5; Power_W: 0.1; Value2: 0.1W; VDC_V: 50; TempCo: 100 ppm/C; SizeArea_mm2: 1.28; SizeX_mm: 1.6; SizeY_mm: 0.8; SizeZ_mm: 1; EIA_Code: E24; U/M: EA; AEC Category: Q200
R47 R48 R52 = CRCW06031K50FKEA: RES, 1.50 k, 1%, 0.1 W, 0603; Manufacturer: Vishay-Dale; CompType: Resistor; Value: 1.50k; Res_ohm: 1500; Value_Code: 1k50; Tolerance_%: 1; Power_W: 0.1; Value2: 0.1W; VDC_V: 75; TempCo: 100 ppm/C; EIA_Code: E96; U/M: EA
R84 R86 = CRCW0603300RJNEA: RES, 300 ohm, 5%, 0.1W, 0603; Manufacturer: Vishay-Dale; CompType: Resistor; Value_Code: 300R; Tolerance_%: 5; Power_W: 0.1; VDC_V: 75; TempCo: 200 ppm/C; EIA_Code: E24; U/M: EA
R91 = CRCW060310K0JNEA: RES, 10 k, 5%, 0.1 W, 0603; Manufacturer: Vishay-Dale; CompType: Resistor; Value: 10k; Res_ohm: 10000; Value_Code: 10k0; Tolerance_%: 5; Power_W: 0.1; Value2: 0.1W; VDC_V: 75; TempCo: 200 ppm/C; SizeArea_mm2: 1.28; SizeX_mm: 1.6; SizeY_mm: 0.8; SizeZ_mm: 1; EIA_Code: E24; U/M: EA; AEC Category: Q200
R99 = CRCW08050000Z0EA: RES, 0, 5%, 0.125 W, 0805; Manufacturer: Vishay-Dale; CompType: Resistor; Value: 0; Value_Code: 0000; Tolerance_%: 5; Power_W: 0.125; Value2: 0.125W; VDC_V: 150; TempCo: 200 ppm/C; SizeArea_mm2: 2.5; SizeX_mm: 2; SizeY_mm: 1.25; SizeZ_mm: 1.45; EIA_Code: E24; U/M: EA; AEC Category: Q200
TP1 TP2 TP6 TP13-TP16 = 5000: Test Point, Miniature, Red, TH; Manufacturer: Keystone; CompType: Test Point Loop; ContactFinish: Silver
TP5 TP7 TP9 TP12 = 5000: Test Point, Miniature, Red, TH; Manufacturer: Keystone; CompType: Test Point Loop; U/M: EA
U1 = LP2985-33DBVR: 100-mA ULTRA-LOW DROPOUT REGULATOR WITH SHUTDOWN, DBV0005A; Alternate PartNumber: LP2985-33DBVT; Manufacturer: Texas Instruments; SymbolCreator: Altium; CompType: IC; U/M: EA
U2 = OPT3006YMF: Ambient Light Sensor, YMF0006A (PICOSTAR-6); Manufacturer: Texas Instruments; SymbolCreator: a0411947; SizeArea_mm2: 0.809776; SizeAreaWB_mm2: 3.611776; SizeX_mm: 0.856; SizeY_mm: 0.946; SizeZ_mm: 0.226; CompType: IC; U/M: EA
U3 = HDC1080DMBR: Low Power, High Accuracy Digital Humidity Sensor with Temperature Sensor, DMB0006A; Alternate PartNumber: HDC1080DMBT; Manufacturer: Texas Instruments; SymbolCreator: a0411947; CompType: IC; U/M: EA
U12 = TMP75BIDR: 1.4V-Capable Temperature Sensor with I2C/SMBus Interface in LM75 Form Factor & Pinout, D0008A (SOIC-8); Manufacturer: Texas Instruments; SymbolCreator: a0411947; SizeArea_mm2: 30.38; SizeAreaWB_mm2: 56.58; SizeX_mm: 4.9; SizeY_mm: 6.2; SizeZ_mm: 1.75; CompType: IC; U/M: EA
U13 = SN74LVC2G32DCTR: Dual 2-Input Positive-OR Gate, DCT0008A; Manufacturer: Texas Instruments; SymbolCreator: a0411947; CompType: IC; U/M: EA
U14 = SN74LVC1G14DCKR: SINGLE SCHMITT-TRIGGER INVERTER, DCK0005A; Alternate PartNumber: SN74LVC1G14DCKT; Manufacturer: Texas Instruments; SymbolCreator: a0799628; CompType: IC; U/M: EA
U15 = TMP007AIYZFR: Infrared Thermopile Sensor with Integrated Math Engine, YZF0008AEAE; Alternate PartNumber: TMP007AIYZFT; Manufacturer: Texas Instruments; SymbolCreator: a0411947; SizeArea_mm2: 2.359296; SizeAreaWB_mm2: 6.431296; SizeX_mm: 1.536; SizeZ_mm: 0.625; CompType: IC; U/M: EA
U17 = LMT87LP: IC, TEMP SENSOR PREC ANLG, TO-92, TH; Manufacturer: TEXAS INSTRUMENTS; SymbolCreator: x0199378
U18 = LM35DM/NOPB: Precision Centigrade Temperature Sensor, 8-pin Narrow SOIC, Pb-Free; Manufacturer: Texas Instruments; PackageTopMarking: NSZXTT*LM35D*M; PowerWise: N; CompType: Temp Sensor IC
U19 = TMP302BDRLR: Pin-Selectable Trip Point 1.4V-Capable Family of Temperature Switches, DRL0006A (SOT-OTHER-6); Alternate PartNumber: TMP302BDRLT; Manufacturer: Texas Instruments; SymbolCreator: Altium; SizeArea_mm2: 2.56; SizeAreaWB_mm2: 6.76; SizeX_mm: 1.6; SizeZ_mm: 0.6; CompType: IC; U/M: EA
U20 = TMP102AIDRL: Low Power Digital Temperature Sensor With SMBus/Two-Wire Serial Interface in SOT563, DRL0006A; Alternate Manufacturer: None; Manufacturer: Texas Instruments; SymbolCreator: a0411947; CompType: IC; U/M: EA
U22 = SN74LVC1G17DCKR: SINGLE SCHMITT-TRIGGER BUFFER, DCK0005A (SOT-5); Alternate PartNumber: SN74LVC1G17DCKT; Manufacturer: Texas Instruments; SymbolCreator: a0799628; SizeArea_mm2: 4.2; SizeAreaWB_mm2: 9.3; SizeX_mm: 2.1; SizeY_mm: 2; SizeZ_mm: 1.1; CompType: IC; U/M: EA

## Sheet TIDA-00811_Pg5.SchDoc
size 431 x 279 mm; Date: Not shown in title block; ApprovedBy: Not shown in title block; CheckedBy: Not shown in title block; Author: Not shown in title block; CompanyName: Not shown in title block; DrawnBy: Srinivasa; Engineer: Not shown in title block; Organization: Not shown in title block; Address1: Not shown in title block; Address2: Not shown in title block; Address3: Not shown in title block; Address4: Not shown in title block; DocumentNumber: 1; Revision: Use project parameter SCH_Rev; SheetNumber: 5; SheetTotal: 6; PageSetup: Record=PageOptions¦CenterHorizontal=True¦CenterVertical=True¦PrintScale=1.00¦XCorrection=1.00¦YCorrection=1.00¦PrintKind=0¦BorderSize=5000000¦LeftOffset=0¦BottomOffset=0¦Orientation=2¦PaperLength=1000¦PaperWidth=1000¦Scale=100¦PaperSource=15¦PrintQuality=600¦MediaType=1¦DitherType=10¦PaperKind=Letter¦PrintScaleMode=1
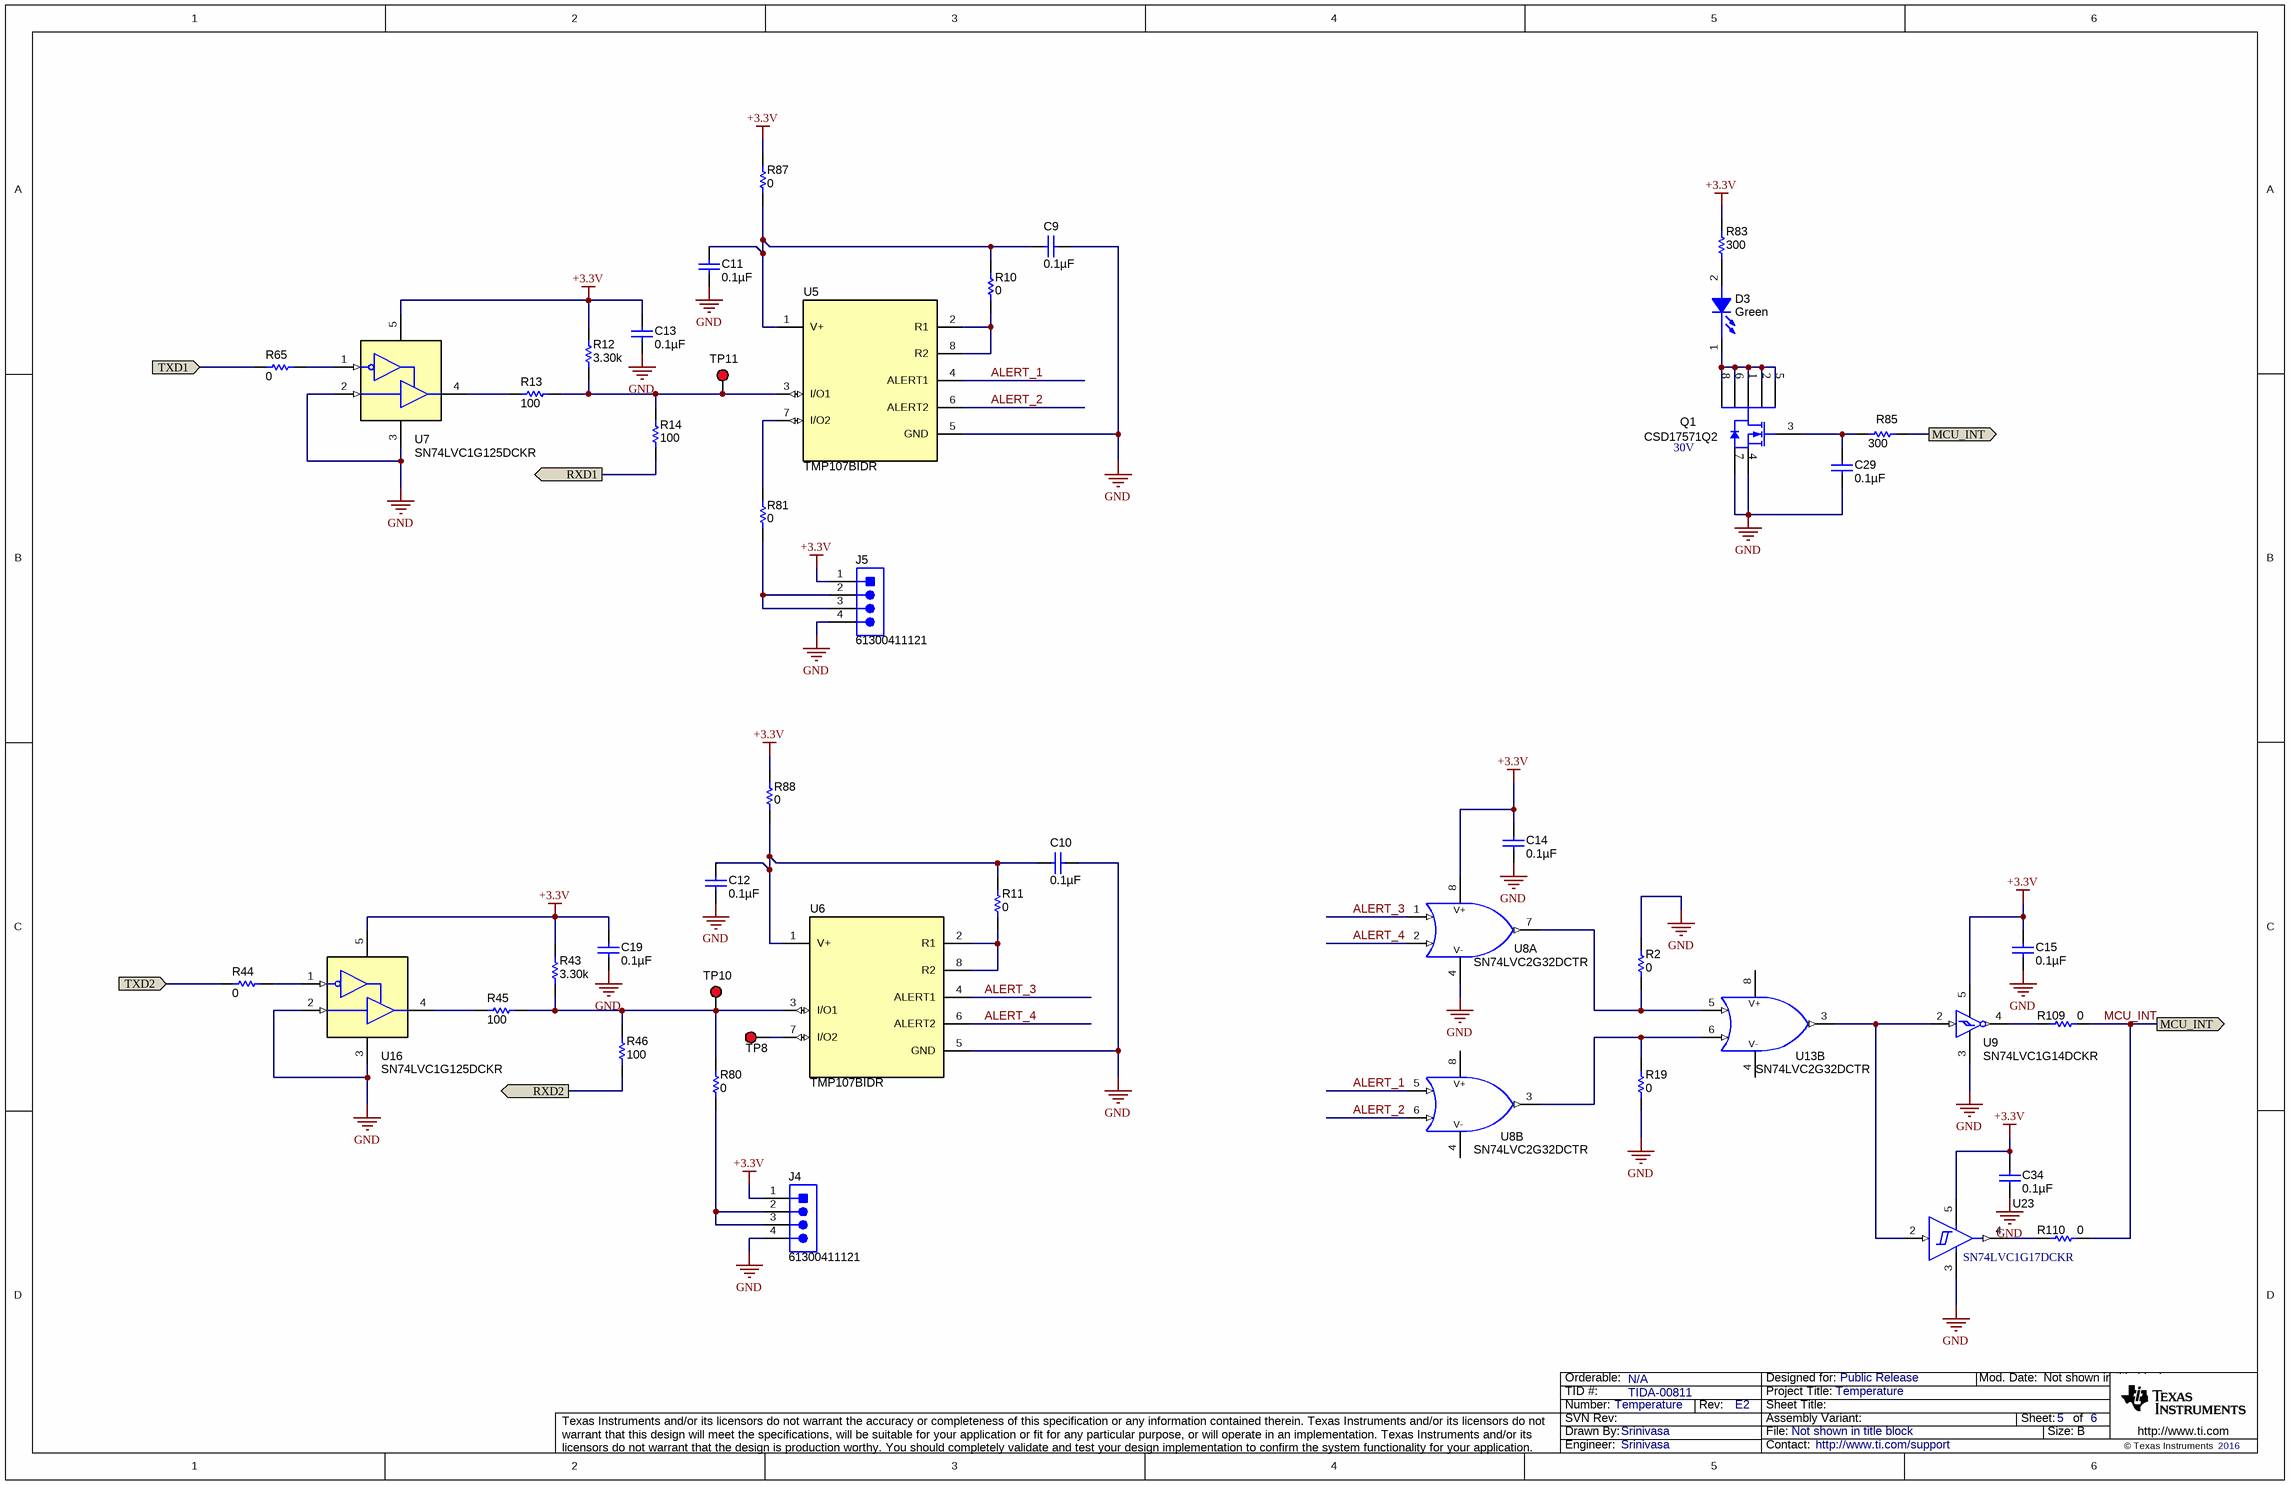
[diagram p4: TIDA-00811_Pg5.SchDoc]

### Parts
C9  ValueDisplayed: 0.1µF  [0603]  (hidden comment: 06033C104JAT2A)
C10  ValueDisplayed: 0.1µF  [0603]  (hidden comment: 06033C104JAT2A)
C11  ValueDisplayed: 0.1µF  [0603]  (hidden comment: 06033C104JAT2A)
C12  ValueDisplayed: 0.1µF  [0603]  (hidden comment: 06033C104JAT2A)
C13  ValueDisplayed: 0.1µF  [0603]  (hidden comment: 06033C104JAT2A)
C14  ValueDisplayed: 0.1µF  [0603]  (hidden comment: 06033C104JAT2A)
C15  ValueDisplayed: 0.1µF  [0603]  (hidden comment: 06033C104JAT2A)
C19  ValueDisplayed: 0.1µF  [0603]  (hidden comment: 06033C104JAT2A)
C29  ValueDisplayed: 0.1µF  [0603]  (hidden comment: 06033C104JAT2A)
C34  ValueDisplayed: 0.1µF  [0603]  (hidden comment: 06033C104JAT2A)
D3  value Green  [LED0603AA]  (hidden comment: LED_LG L29K-G2J1-24-Z)
J4  61300411121  [Mill-Max_342-xx-104-00-592000]
J5  61300411121  [Mill-Max_342-xx-104-00-592000]
Q1  CSD17571Q2  value 30V  [SON_CSD17571Q2]
R2  ValueDisplayed: 0  [0603]  (hidden comment: RC0603JR-070RL)
R10  ValueDisplayed: 0  [0603]  (hidden comment: RC0603JR-070RL)
R11  ValueDisplayed: 0  [0603]  (hidden comment: RC0603JR-070RL)
R12  ValueDisplayed: 3.30k  [0603]  (hidden comment: RC0603FR-073K3L)
R13  ValueDisplayed: 100  [0603]  (hidden comment: RC0603FR-07100RL)
R14  ValueDisplayed: 100  [0603]  (hidden comment: RC0603FR-07100RL)
R19  ValueDisplayed: 0  [0603]  (hidden comment: RC0603JR-070RL)
R43  ValueDisplayed: 3.30k  [0603]  (hidden comment: RC0603FR-073K3L)
R44  ValueDisplayed: 0  [0603]  (hidden comment: RC0603JR-070RL)
R45  ValueDisplayed: 100  [0603]  (hidden comment: RC0603FR-07100RL)
R46  ValueDisplayed: 100  [0603]  (hidden comment: RC0603FR-07100RL)
R65  ValueDisplayed: 0  [0603]  (hidden comment: RC0603JR-070RL)
R80  ValueDisplayed: 0  [0603]  (hidden comment: RC0603JR-070RL)
R81  ValueDisplayed: 0  [0603]  (hidden comment: RC0603JR-070RL)
R83  value 300  [0603]  (hidden comment: CRCW0603300RJNEA)
R85  value 300  [0603]  (hidden comment: CRCW0603300RJNEA)
R87  ValueDisplayed: 0  [0603]  (hidden comment: RC0603JR-070RL)
R88  ValueDisplayed: 0  [0603]  (hidden comment: RC0603JR-070RL)
R109  ValueDisplayed: 0  [0603]  (hidden comment: RC0603JR-070RL)
R110  ValueDisplayed: 0  [0603]  (hidden comment: RC0603JR-070RL)
TP8  5000  [Keystone5000]  (value not drawn)
TP10  5000  [Keystone5000]  (value not drawn)
TP11  5000  [Keystone5000]  (value not drawn)
U5  TMP107BIDR  [D0008A_N]
U6  TMP107BIDR  [D0008A_N]
U7  SN74LVC1G125DCKR  [DCK0005A_N]
U8  SN74LVC2G32DCTR  [DCT0008A_N]  (parts A,B of 2)
U9  SN74LVC1G14DCKR  [DCK0005A_N]
U13  SN74LVC2G32DCTR  [DCT0008A_N]  (part B of 2)
U16  SN74LVC1G125DCKR  [DCK0005A_N]
U23  SN74LVC1G17DCKR  [DCK0005A_N]

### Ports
MCU_INT (out), RXD1 (out), RXD2 (out), TXD1 (in), TXD2 (in)

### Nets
+3.3V: C13.2 C14.2 C15.2 C19.2 C34.2 J4.1 J5.1 R12.2 R43.2 R83.2 R87.1 R88.1 U7.5(VCC) U8.8(VCC) U9.5(VCC) U13.8(VCC) U16.5(VCC) U23.5(VCC)
GND: C9.2 C10.2 C11.1 C12.1 C13.1 C14.1 C15.1 C19.1 C29.2 C34.1 J4.4 J5.4 Q1.4(S) Q1.7(S) R2.2 R19.1 U5.5(GND) U6.5(GND) U7.2(A) U7.3(GND) U8.4(GND) U9.3(GND) U13.4(GND) U16.2(A) U16.3(GND) U23.3(GND)
ALERT_1: U5.4(ALERT1) U8.5(2A)
ALERT_2: U5.6(ALERT2) U8.6(2B)
ALERT_3: U6.4(ALERT1) U8.1(1A)
ALERT_4: U6.6(ALERT2) U8.2(1B)
MCU_INT: R85.1 R109.2 R110.2 ; port MCU_INT
RXD1: R14.1 ; port RXD1
RXD2: R46.1 ; port RXD2
TXD1: R65.2 ; port TXD1
TXD2: R44.2 ; port TXD2
NetC9_1: C9.1 C11.2 R10.1 R87.2 U5.1(V+)
NetC10_1: C10.1 C12.2 R11.1 R88.2 U6.1(V+)
NetC29_1: C29.1 Q1.3(G) R85.2
NetD3_1: D3.1(C) Q1.1(D) Q1.2(D) Q1.5(D) Q1.6(D) Q1.8(D)
NetD3_2: D3.2(A) R83.1
NetJ4_2: J4.2 J4.3 R80.1
NetJ5_2: J5.2 J5.3 R81.2
NetR2_1: R2.1 U8.7(1Y) U13.5(2A)
NetR10_2: R10.2 U5.2(R1) U5.8(R2)
NetR11_2: R11.2 U6.2(R1) U6.8(R2)
NetR12_1: R12.1 R13.2 R14.2 TP11.1 U5.3(I/O1)
NetR13_1: R13.1 U7.4(Y)
NetR19_2: R19.2 U8.3(2Y) U13.6(2B)
NetR43_1: R43.1 R45.2 R46.2 R80.2 TP10.1 U6.3(I/O1)
NetR44_1: R44.1 U16.1(~{OE})
NetR45_1: R45.1 U16.4(Y)
NetR65_1: R65.1 U7.1(~{OE})
NetR81_1: R81.1 U5.7(I/O2)
NetR109_1: R109.1 U9.4(Y)
NetR110_1: R110.1 U23.4(Y)
NetTP8_1: TP8.1 U6.7(I/O2)
NetU9_2: U9.2(A) U13.3(2Y) U23.2(A)

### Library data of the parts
C9-C15 C19 C34 = 06033C104JAT2A: as C8 on sheet TIDA-00811_Pg3
C29 = 06033C104JAT2A: as C22 on sheet TIDA-00811_Pg4
D3 = LED_LG L29K-G2J1-24-Z: as D4 on sheet TIDA-00811_Pg4
J4 J5 = 342-10-104-00-592000: Header, 2.54mm, 4x1, Gold, TH; Manufacturer: Mill-Max; SymbolCreator: a0412235; Pitch_mm: 2.54; Gender: Male; Shrouded: N; Row_Count: 1
Q1 = CSD17571Q2: as Q2 on sheet TIDA-00811_Pg4
R2 R10 R11 R19 R44 R65 R80 R81 R87 R88 R109 R110 = RC0603JR-070RL: as R20 on sheet TIDA-00811_Pg4
R12 R43 = RC0603FR-073K3L: RES, 3.30 k, 1%, 0.1 W, 0603; Manufacturer: Yageo America; CompType: Resistor; Value: 3.30k; Res_ohm: 3300; Value_Code: 3k30; Tolerance_%: 1; Power_W: 0.1; Value2: 0.1W; VDC_V: 150; TempCo: 200 ppm/C; U/M: EA; AEC Category: Q200
R13 R14 R45 R46 = RC0603FR-07100RL: RES, 100, 1%, 0.1 W, 0603; Manufacturer: Yageo America; CompType: Resistor; Value: 100; Value_Code: 100R; Tolerance_%: 1; Power_W: 0.1; Value2: 0.1W; VDC_V: 150; TempCo: 200 ppm/C; EIA_Code: E96; U/M: EA; AEC Category: Q200
R83 R85 = CRCW0603300RJNEA: as R84 on sheet TIDA-00811_Pg4
TP8 TP10 TP11 = 5000: as TP1 on sheet TIDA-00811_Pg4
U5 U6 = TMP107BIDR: TMP107B, D0008A; Manufacturer: Texas Instruments; SymbolCreator: Altium; CompType: IC; U/M: EA
U7 U16 = SN74LVC1G125DCKR: Single Bus Buffer Gate With 3-State Output, DCK0005A; Alternate PartNumber: SN74LVC1G125DCKT; Manufacturer: Texas Instruments; SymbolCreator: Altium; CompType: IC; U/M: EA
U8 U13 = SN74LVC2G32DCTR: as U13 on sheet TIDA-00811_Pg4
U9 = SN74LVC1G14DCKR: as U14 on sheet TIDA-00811_Pg4
U23 = SN74LVC1G17DCKR: as U22 on sheet TIDA-00811_Pg4

## Sheet TIDA-00811_Pg6_EVM_Hardware.SchDoc
size 431 x 279 mm; Date: Not shown in title block; ApprovedBy: Not shown in title block; CheckedBy: Not shown in title block; Author: Not shown in title block; CompanyName: Not shown in title block; DrawnBy: Srinivasa; Engineer: Not shown in title block; Organization: Not shown in title block; Address1: Not shown in title block; Address2: Not shown in title block; Address3: Not shown in title block; Address4: Not shown in title block; DocumentNumber: 1; Revision: Use project parameter SCH_Rev; SheetNumber: 6; SheetTotal: 6; PageSetup: Record=PageOptions¦CenterHorizontal=True¦CenterVertical=True¦PrintScale=1.00¦XCorrection=1.00¦YCorrection=1.00¦PrintKind=0¦BorderSize=5000000¦LeftOffset=0¦BottomOffset=0¦Orientation=2¦PaperLength=1000¦PaperWidth=1000¦Scale=100¦PaperSource=15¦PrintQuality=600¦MediaType=1¦DitherType=10¦PaperKind=Letter¦PrintScaleMode=1
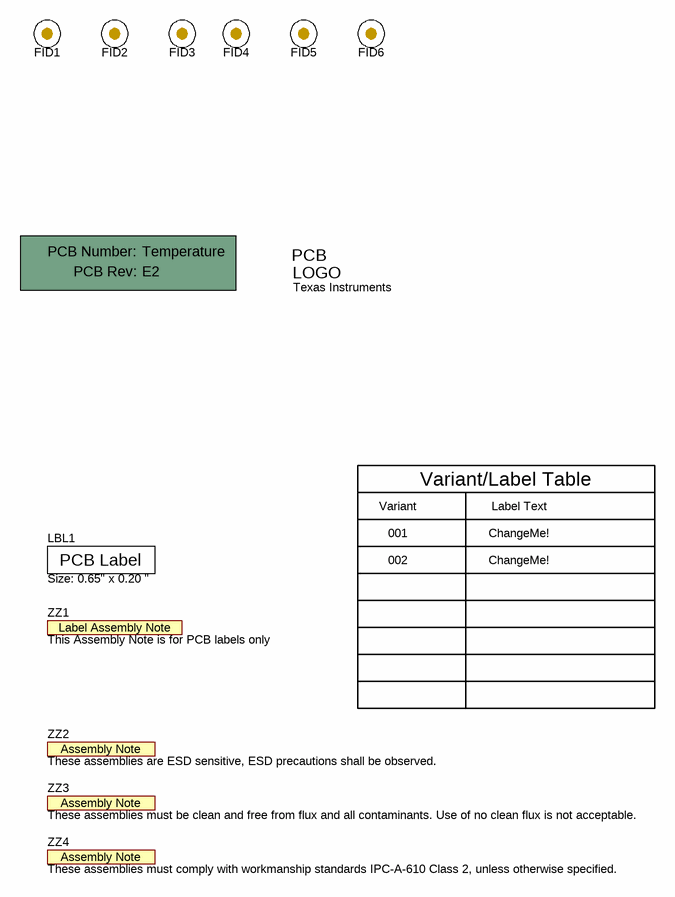
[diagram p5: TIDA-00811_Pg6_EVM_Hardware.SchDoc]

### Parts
!PCB1  Printed Circuit Board  (value not drawn)  (mechanical)
FID1  Fiducial  [Fiducial10-20]  (value not drawn)
FID2  Fiducial  [Fiducial10-20]  (value not drawn)
FID3  Fiducial  [Fiducial10-20]  (value not drawn)
FID4  Fiducial  [Fiducial10-20]  (value not drawn)
FID5  Fiducial  [Fiducial10-20]  (value not drawn)
FID6  Fiducial  [Fiducial10-20]  (value not drawn)
LBL1  Size: 0.65" x 0.20 "  [Label_650x200]
Logo1  Texas Instruments  [TI_Stacked_Overlay_Small]  (no BOM)
ZZ1  This Assembly Note is for PCB labels only  [AssemblyNoteLabel]  (no BOM)
ZZ2  These assemblies are ESD sensitive, ESD precautions shall be observed.  [AssemblyNote]  (no BOM)
ZZ3  These assemblies must be clean and free from flux and all contaminants. Use of no clean flux is not acceptable.  [AssemblyNote]  (no BOM)
ZZ4  These assemblies must comply with workmanship standards IPC-A-610 Class 2, unless otherwise specified.  [AssemblyNote]  (no BOM)

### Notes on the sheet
- Variant
- Variant/Label Table
- Label Text
- 001
- 002
- ChangeMe!

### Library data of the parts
!PCB1 = PCB: Manufacturer: Any; PartNumber: Temperature; SymbolCreator: a0412235
FID1-FID6 = Fiducial: Fiducial mark.  There is nothing to buy or mount.; SymbolCreator: codlsc
LBL1 = THT-14-423-10: Thermal Transfer Printable Labels, 0.650" W x 0.200" H - 10,000 per roll; Manufacturer: Brady; SymbolCreator: a0412235; CompType: Label
Logo1 = TI_Logo: Texas Instrument Corporate Signature; SymbolCreator: codlsc
ZZ1 = AssemblyNoteLabel: SymbolCreator: a0412235
ZZ2-ZZ4 = AssemblyNote: SymbolCreator: codlsc

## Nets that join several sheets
+3.3V: TIDA-00811_Pg3 (12 pins), TIDA-00811_Pg4 (29 pins), TIDA-00811_Pg5 (18 pins)
GND: TIDA-00811_Pg3 (8 pins), TIDA-00811_Pg4 (51 pins), TIDA-00811_Pg5 (26 pins)
DC_IN: TIDA-00811_Pg3 (J2.5), TIDA-00811_Pg4 (6 pins)
I2C_SCL: TIDA-00811_Pg3 (R5.1 R73.2 TP3.1 U4.2), TIDA-00811_Pg4 (5 pins)
I2C_SDA: TIDA-00811_Pg3 (R4.1 R72.2 TP4.1 U4.3), TIDA-00811_Pg4 (5 pins)
MCU_INT: TIDA-00811_Pg3 (J1.5), TIDA-00811_Pg5 (R85.1 R109.2 R110.2)
MCU_INT1: TIDA-00811_Pg3 (J1.6), TIDA-00811_Pg4 (R86.1 R107.2 R108.2)
RXD1: TIDA-00811_Pg3 (U11.1), TIDA-00811_Pg5 (R14.1)
RXD2: TIDA-00811_Pg3 (U11.3), TIDA-00811_Pg5 (R46.1)
TXD1: TIDA-00811_Pg3 (U10.1), TIDA-00811_Pg5 (R65.2)
TXD2: TIDA-00811_Pg3 (U10.3), TIDA-00811_Pg5 (R44.2)

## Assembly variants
001: not fitted C29 C30 FID1 FID2 FID3 FID4 FID5 FID6 R2 R15 R16 R19 R28 R31 R32 R33 R34 R35 R37 R40 R41 R42 R49 R50 R51 R53 R54 R68 R72 R73 R78 R79 R93 R94 R95 R99 R108 R110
